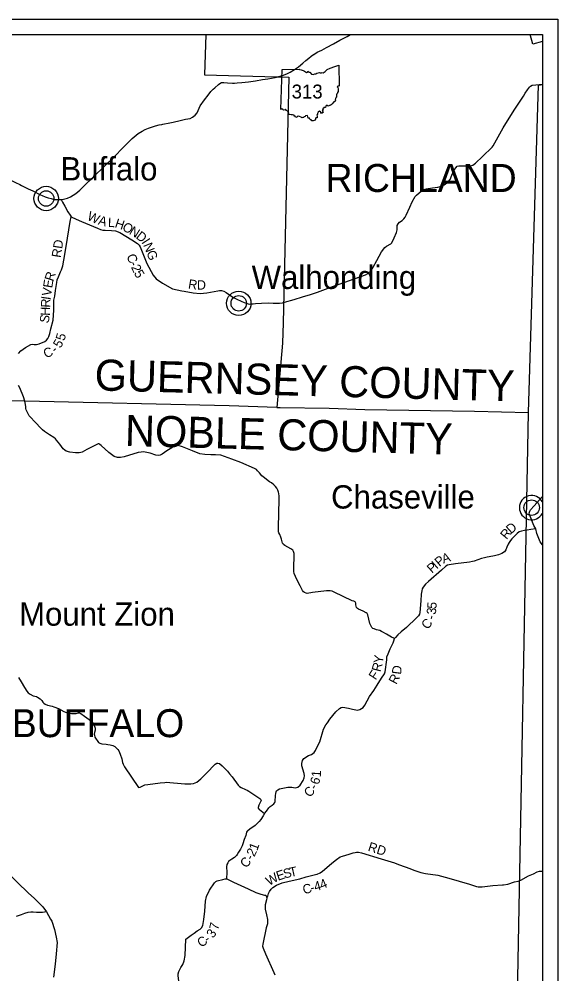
# Model space of a CAD drawing. Extents: x -452339 to 6403467, y -1 to 1814750.
# Drawn here: x -362512 to -345163, y 1631137 to 1661857 of the extents above; entities that cross this region are included whole.
import ezdxf

# ---------------------------------------------------------------- set-up
doc = ezdxf.new("R2010")
doc.units = 0
for name, color, linetype in [('Default', 7, 'Continuous'), ('GM_X_Adjacent_County_Text', 7, 'Continuous'), ('GM_X_County', 7, 'Continuous'), ('GM_X_County_Road', 7, 'Continuous'), ('GM_X_County_Road_Text', 7, 'Continuous'), ('GM_X_Minor_River_Text', 7, 'Continuous'), ('GM_X_Section', 7, 'Continuous'), ('GM_X_Section_Text', 7, 'Continuous'), ('GM_X_Township_Subdivision_Text', 7, 'Continuous')]:
    doc.layers.add(name, color=color, linetype=linetype)

msp = doc.modelspace()

# ---------------------------------------------------------------- linework, layer by layer
at = {"layer": 'Default'}
for p, q in [((-403040, 1661357), (-345663, 1661357)), ((-345663, 1661357), (-345663, 1603979)), ((-354084, 1658949), (-354043, 1660240))]:
    msp.add_line(p, q, dxfattribs=at)
msp.add_lwpolyline([(-403540, 1661857), (-345163, 1661857), (-345163, 1603479), (-403540, 1603479)], close=True, dxfattribs=at)
for points in [[(-354043, 1660240), (-353470, 1660248), (-353479, 1660232), (-353425, 1660229), (-353368, 1660202), (-353319, 1660184), (-353260, 1660143), (-353225, 1660144), (-353210, 1660178), (-353183, 1660151), (-353150, 1660147), (-353094, 1660085), (-353048, 1660072), (-352993, 1660093), (-352952, 1660096), (-352922, 1660117), (-352843, 1660135), (-352821, 1660124), (-352779, 1660127), (-352758, 1660135), (-352722, 1660127), (-352659, 1660175), (-352593, 1660230), (-352492, 1660282), (-352341, 1660331), (-352221, 1660376), (-352204, 1659705)], [(-353036, 1653028), (-352904, 1653069), (-352385, 1653265), (-351363, 1653626), (-351278, 1653673), (-351177, 1653770), (-351108, 1653878), (-350990, 1654089), (-350840, 1654366), (-350735, 1654511), (-350682, 1654554), (-350540, 1654623), (-350507, 1654661), (-350432, 1654816), (-350360, 1654990), (-350335, 1655078), (-350338, 1655170), (-350334, 1655214), (-350310, 1655274), (-350265, 1655319), (-350181, 1655382), (-350128, 1655428), (-350082, 1655488), (-350047, 1655553), (-349933, 1655808), (-349855, 1655980), (-349762, 1656147), (-349719, 1656193), (-349554, 1656333), (-349494, 1656371), (-349401, 1656400), (-349197, 1656426), (-349033, 1656452), (-348955, 1656468), (-348822, 1656528), (-348712, 1656607), (-348633, 1656695), (-348574, 1656838), (-348526, 1656964), (-348483, 1657032), (-348455, 1657075), (-348411, 1657121), (-348355, 1657138), (-347981, 1657131), (-347899, 1657152), (-347818, 1657217), (-347592, 1657431), (-347284, 1657733), (-347243, 1657782), (-347196, 1657880), (-346922, 1658358), (-346567, 1658929), (-346273, 1659378), (-346217, 1659469), (-346143, 1659577), (-346077, 1659665), (-346042, 1659700), (-345992, 1659728), (-345876, 1659743), (-345663, 1659759)], [(-352204, 1659705), (-352222, 1659696), (-352249, 1659701), (-352267, 1659682), (-352244, 1659651), (-352234, 1659617), (-352243, 1659581), (-352234, 1659551), (-352240, 1659526), (-352257, 1659500), (-352263, 1659477), (-352278, 1659451), (-352277, 1659437), (-352291, 1659426), (-352288, 1659384), (-352295, 1659361), (-352293, 1659341), (-352316, 1659336), (-352311, 1659319), (-352325, 1659306), (-352322, 1659284), (-352338, 1659270), (-352323, 1659242), (-352335, 1659233), (-352346, 1659199), (-352375, 1659192), (-352433, 1659130), (-352454, 1659106), (-352476, 1659100), (-352489, 1659076), (-352518, 1659076), (-352561, 1659059), (-352589, 1659088), (-352637, 1659053), (-352643, 1659013), (-352704, 1659014), (-352702, 1658994), (-352716, 1658988), (-352728, 1658968), (-352721, 1658931), (-352750, 1658922), (-352746, 1658901), (-352728, 1658888), (-352720, 1658848), (-352750, 1658856), (-352775, 1658822), (-352801, 1658830), (-352793, 1658859), (-352837, 1658894), (-352878, 1658866), (-352899, 1658822), (-352900, 1658792), (-352930, 1658774), (-352910, 1658732), (-352914, 1658703), (-352914, 1658675), (-352952, 1658676), (-352976, 1658602)], [(-352976, 1658602), (-353042, 1658588), (-353088, 1658580), (-353105, 1658613), (-353138, 1658631), (-353160, 1658665), (-353207, 1658669), (-353218, 1658716), (-353224, 1658754), (-353289, 1658745), (-353306, 1658721), (-353330, 1658715), (-353343, 1658692), (-353375, 1658690), (-353409, 1658679), (-353431, 1658702), (-353486, 1658725), (-353511, 1658737), (-353563, 1658718), (-353574, 1658696), (-353615, 1658706), (-353625, 1658730), (-353650, 1658738), (-353656, 1658763), (-353709, 1658777), (-353750, 1658772), (-353822, 1658792), (-353827, 1658826), (-353852, 1658867), (-353864, 1658896), (-353910, 1658918), (-353919, 1658952), (-353934, 1658951), (-353947, 1658937), (-353998, 1658931), (-354018, 1658944), (-354047, 1658968), (-354084, 1658949)], [(-361158, 1656055), (-361115, 1655967), (-361042, 1655834), (-360943, 1655660), (-360871, 1655545), (-360838, 1655500), (-360678, 1655421), (-360498, 1655343), (-359990, 1655125), (-359895, 1655088), (-359820, 1655071), (-359741, 1655063), (-359535, 1655058), (-359411, 1655045), (-359272, 1654990), (-358878, 1654758), (-358694, 1654634), (-358642, 1654578), (-358616, 1654529), (-358400, 1653988), (-358190, 1653618), (-358097, 1653500), (-357891, 1653357), (-357573, 1653183), (-357273, 1653116), (-357194, 1653100), (-356909, 1653045), (-356677, 1653031), (-356466, 1653046), (-356113, 1653113), (-356064, 1653121), (-355998, 1653123), (-355924, 1653105), (-355849, 1653060), (-355633, 1652907), (-355505, 1652848), (-355365, 1652777), (-355269, 1652734), (-355139, 1652691), (-355096, 1652687), (-355028, 1652693), (-354973, 1652693), (-354900, 1652708), (-354705, 1652721), (-354470, 1652723), (-354332, 1652720), (-354230, 1652713), (-354132, 1652718), (-354034, 1652730), (-353993, 1652742), (-353963, 1652751)], [(-362527, 1651103), (-362460, 1651181), (-362302, 1651291), (-362135, 1651383), (-362085, 1651396), (-362029, 1651390), (-361952, 1651383), (-361868, 1651412), (-361681, 1651487), (-361627, 1651529), (-361585, 1651584), (-361554, 1651642), (-361521, 1651746), (-361493, 1651893), (-361414, 1652169), (-361398, 1652493), (-361398, 1652704), (-361389, 1652809), (-361360, 1652940), (-361339, 1653125), (-361301, 1653386), (-361284, 1653466), (-361246, 1653567), (-361179, 1653727), (-361145, 1653790), (-361103, 1653921), (-361036, 1654279), (-360958, 1654810), (-360868, 1655343), (-360838, 1655500)], [(-353963, 1652751), (-353654, 1652840), (-353385, 1652923), (-353134, 1652998), (-353036, 1653028)], [(-362329, 1649567), (-362373, 1649707), (-362491, 1649998), (-362527, 1650069)], [(-345871, 1645453), (-346031, 1645431), (-346156, 1645411), (-346244, 1645400), (-346340, 1645382), (-346415, 1645356), (-346480, 1645305), (-346564, 1645223), (-346647, 1645134), (-346694, 1645078), (-346733, 1645019), (-346764, 1644961), (-346803, 1644863), (-346838, 1644784), (-346858, 1644748), (-346887, 1644714), (-346964, 1644667), (-347080, 1644619), (-347207, 1644590), (-347375, 1644560), (-347446, 1644547), (-347530, 1644524), (-347622, 1644501), (-347864, 1644418), (-347916, 1644403), (-348012, 1644384), (-348459, 1644326), (-348662, 1644296), (-348714, 1644285), (-348769, 1644256), (-348910, 1644131), (-349326, 1643766), (-349423, 1643677), (-349500, 1643580), (-349531, 1643522), (-349546, 1643464), (-349563, 1643350), (-349578, 1643138), (-349613, 1642768), (-349621, 1642710), (-349648, 1642658), (-349711, 1642589), (-350043, 1642282), (-350205, 1642138), (-350313, 1642045), (-350394, 1641955), (-350426, 1641932), (-350450, 1641938), (-350516, 1641976), (-350681, 1642068), (-350798, 1642128), (-350838, 1642158), (-350896, 1642181), (-351009, 1642207), (-351081, 1642234), (-351121, 1642252), (-351154, 1642287), (-351217, 1642406), (-351283, 1642687), (-351307, 1642735), (-351334, 1642758), (-351430, 1642811), (-351581, 1642867), (-351621, 1642892), (-351647, 1642930), (-351665, 1643015), (-351671, 1643061), (-351683, 1643085), (-351696, 1643103), (-351730, 1643124), (-351786, 1643140), (-352082, 1643284), (-352365, 1643422), (-352427, 1643447), (-352492, 1643462), (-352617, 1643458), (-353068, 1643403), (-353232, 1643379), (-353272, 1643382), (-353324, 1643405), (-353350, 1643433), (-353383, 1643474), (-353459, 1643627), (-353543, 1643782), (-353614, 1643923), (-353656, 1644018), (-353668, 1644082), (-353670, 1644237), (-353655, 1644571), (-353652, 1644661), (-353662, 1644697), (-353673, 1644725), (-353701, 1644768), (-353764, 1644811), (-353955, 1644925), (-353995, 1644952), (-354014, 1644972), (-354028, 1644999), (-354060, 1645125), (-354086, 1645192), (-354119, 1645274), (-354150, 1645333), (-354158, 1645359), (-354163, 1645515), (-354140, 1646397), (-354141, 1646437), (-354143, 1646509), (-354145, 1646595), (-354163, 1646637), (-354184, 1646696), (-354215, 1646760), (-354253, 1646817), (-354306, 1646872), (-354383, 1646933), (-354449, 1646974), (-354546, 1647043), (-354613, 1647094), (-354691, 1647163), (-354775, 1647258), (-354833, 1647325), (-354868, 1647362), (-354928, 1647402), (-355376, 1647595), (-355657, 1647702), (-355898, 1647788), (-356021, 1647823), (-356190, 1647837), (-356334, 1647833), (-356535, 1647845), (-356693, 1647874), (-356929, 1647961), (-357245, 1648092), (-357385, 1648139), (-357446, 1648138), (-357525, 1648105), (-357597, 1648065), (-357752, 1647963), (-357910, 1647854), (-357967, 1647825), (-358015, 1647815), (-358108, 1647830), (-358295, 1647892), (-358401, 1647915), (-358510, 1647932), (-358578, 1647927), (-358680, 1647912), (-359127, 1647770), (-359249, 1647747), (-359345, 1647750), (-359450, 1647787), (-359622, 1647913), (-359864, 1648142), (-359909, 1648174), (-359935, 1648186), (-359963, 1648189), (-360011, 1648175), (-360328, 1648004), (-360485, 1647925), (-360521, 1647912), (-360579, 1647904), (-360694, 1647903), (-360874, 1647923), (-360993, 1647954), (-361041, 1647983), (-361094, 1648033), (-361205, 1648183), (-361303, 1648310), (-361343, 1648354), (-361396, 1648399), (-361535, 1648484), (-361694, 1648586), (-361763, 1648642), (-361828, 1648717), (-361960, 1648861), (-362182, 1649087), (-362282, 1649287), (-362291, 1649324), (-362297, 1649385), (-362309, 1649454), (-362329, 1649567)], [(-354219, 1637028), (-354219, 1637029), (-354214, 1637039), (-354182, 1637061), (-354129, 1637091), (-353965, 1637127), (-353861, 1637147), (-353728, 1637146), (-353620, 1637125), (-353532, 1637148), (-353460, 1637206), (-353367, 1637357), (-353334, 1637442), (-353318, 1637506), (-353331, 1637582), (-353403, 1637832), (-353411, 1637904), (-353390, 1638004), (-353342, 1638065), (-353191, 1638160), (-353099, 1638201), (-353009, 1638265), (-352964, 1638324), (-352905, 1638463), (-352826, 1638607), (-352710, 1639009), (-352631, 1639148), (-352580, 1639220), (-352504, 1639335), (-352310, 1639569), (-352196, 1639672), (-352139, 1639712), (-352089, 1639719), (-351902, 1639682), (-351772, 1639657), (-351619, 1639626), (-351545, 1639642), (-351491, 1639677), (-351431, 1639703), (-351380, 1639778), (-351224, 1640061), (-351093, 1640259), (-350982, 1640432), (-350843, 1640647), (-350746, 1640792), (-350723, 1640858), (-350675, 1641247), (-350666, 1641334), (-350631, 1641432), (-350564, 1641591), (-350471, 1641786), (-350445, 1641858), (-350426, 1641932)], [(-362533, 1640668), (-362449, 1640537), (-362336, 1640349), (-362266, 1640236), (-362219, 1640183), (-362160, 1640132), (-362061, 1640085), (-361951, 1640059), (-361915, 1640042), (-361836, 1639985), (-361783, 1639928), (-361748, 1639885), (-361719, 1639845), (-361675, 1639818), (-361596, 1639787), (-361444, 1639752), (-361389, 1639731), (-361241, 1639673), (-361069, 1639580), (-360964, 1639536), (-360902, 1639529), (-360824, 1639513), (-360678, 1639515), (-360596, 1639533), (-360568, 1639537), (-360528, 1639520), (-360408, 1639434), (-360178, 1639264), (-360147, 1639232), (-360104, 1639149), (-360078, 1639080), (-360066, 1639038), (-360065, 1638982), (-360083, 1638899), (-360091, 1638855), (-360088, 1638813), (-360073, 1638755), (-359958, 1638583), (-359915, 1638556), (-359843, 1638543), (-359707, 1638531), (-359655, 1638522), (-359581, 1638512), (-359492, 1638485), (-359432, 1638458), (-359381, 1638407), (-359330, 1638354), (-359299, 1638310), (-359252, 1638211), (-359201, 1638052), (-359179, 1637938), (-359164, 1637890), (-359114, 1637795), (-358666, 1637130), (-358609, 1637145), (-358506, 1637197), (-358461, 1637218), (-358367, 1637236), (-357974, 1637283), (-357822, 1637298), (-357776, 1637302), (-357173, 1637253), (-356985, 1637251), (-356896, 1637266), (-356786, 1637310), (-356662, 1637415), (-356475, 1637596), (-356200, 1637880), (-356143, 1637915), (-356113, 1637917), (-356061, 1637904), (-355977, 1637831), (-355914, 1637764), (-355803, 1637661), (-355732, 1637571), (-355650, 1637473), (-355461, 1637212), (-355415, 1637164), (-355361, 1637129), (-355218, 1637068), (-355168, 1637046), (-355110, 1637016), (-354757, 1636780), (-354727, 1636749), (-354719, 1636725), (-354723, 1636698), (-354788, 1636568), (-354815, 1636493), (-354811, 1636471), (-354779, 1636426), (-354777, 1636424)], [(-354608, 1636296), (-354542, 1636377), (-354467, 1636484), (-354431, 1636524), (-354361, 1636571), (-354307, 1636613), (-354278, 1636647), (-354262, 1636688), (-354255, 1636878), (-354248, 1636942), (-354234, 1636994), (-354219, 1637028)], [(-354777, 1636424), (-354775, 1636422), (-354608, 1636296), (-354655, 1636226), (-354732, 1636109), (-354780, 1636039), (-354810, 1636005), (-354911, 1635916), (-355079, 1635792), (-355150, 1635742), (-355166, 1635726), (-355186, 1635695), (-355215, 1635593), (-355265, 1635456), (-355310, 1635320), (-355333, 1635261), (-355387, 1635153), (-355444, 1635056), (-355485, 1634978), (-355509, 1634946), (-355581, 1634881), (-355665, 1634828), (-355722, 1634788), (-355764, 1634757), (-355792, 1634709), (-355818, 1634655), (-355829, 1634583), (-355828, 1634408), (-355834, 1634196), (-355806, 1634180), (-355609, 1634089), (-355141, 1633872), (-354888, 1633758), (-354729, 1633703), (-354605, 1633674), (-354571, 1633666), (-354532, 1633580), (-354548, 1633524), (-354584, 1633355), (-354592, 1633273), (-354585, 1633225), (-354548, 1633039), (-354515, 1632883), (-354513, 1632831), (-354518, 1632750), (-354553, 1632616), (-354661, 1632094), (-354673, 1632034), (-354655, 1631964), (-354579, 1631784), (-354306, 1631181), (-354274, 1631105)], [(-354532, 1633580), (-354506, 1633642), (-354477, 1633725), (-354445, 1633787), (-354392, 1633861), (-354338, 1633916), (-354226, 1633987), (-354037, 1634066), (-353813, 1634124), (-353471, 1634200), (-353265, 1634256), (-352971, 1634330), (-352913, 1634349), (-352817, 1634391), (-352742, 1634446), (-352608, 1634563), (-352439, 1634701), (-352288, 1634820), (-352174, 1634899), (-352098, 1634929), (-351884, 1634991), (-351760, 1635030), (-351696, 1635046), (-351650, 1635055), (-351584, 1635055), (-351482, 1635034), (-350852, 1634840), (-350428, 1634709), (-350299, 1634658), (-350085, 1634583), (-349928, 1634530), (-349797, 1634477), (-349641, 1634416), (-349581, 1634396), (-349422, 1634371), (-349025, 1634314), (-348678, 1634216), (-348012, 1634020), (-347789, 1633954), (-347735, 1633942), (-347606, 1633943), (-347254, 1633976), (-346951, 1634003), (-346912, 1634006)], [(-346912, 1634006), (-346774, 1634019), (-346558, 1634099), (-346448, 1634120), (-346357, 1634157), (-346113, 1634295), (-345951, 1634360), (-345830, 1634420), (-345754, 1634441), (-345663, 1634445)], [(-361633, 1633132), (-361756, 1633116), (-361884, 1633109), (-361956, 1633114), (-362062, 1633125), (-362138, 1633123), (-362230, 1633110), (-362334, 1633083), (-362445, 1633040), (-362605, 1632985)], [(-357270, 1628817), (-357270, 1628818), (-357265, 1628856), (-357275, 1628936), (-357318, 1629084), (-357332, 1629193), (-357324, 1629407), (-357306, 1629605), (-357300, 1629697), (-357296, 1630170), (-357303, 1630602), (-357311, 1630676), (-357363, 1630918), (-357387, 1631075), (-357387, 1631139), (-357373, 1631213), (-357301, 1631343), (-357237, 1631443), (-357192, 1631553), (-357162, 1631726), (-357141, 1632254)]]:
    msp.add_lwpolyline(points, dxfattribs=at)
at = {"layer": 'GM_X_County_Road'}
for points in [[(-357880, 1658474), (-357828, 1658484), (-357711, 1658507), (-357547, 1658543), (-357329, 1658592), (-357154, 1658633), (-357006, 1658658), (-356924, 1658699), (-356839, 1658764), (-356774, 1658846), (-356679, 1659070), (-356539, 1659264), (-356427, 1659412), (-356336, 1659527), (-356265, 1659603), (-356212, 1659646), (-356096, 1659752), (-356047, 1659789), (-355995, 1659812), (-355921, 1659815), (-355805, 1659809), (-355642, 1659793), (-355572, 1659791), (-355488, 1659802), (-355338, 1659818), (-355130, 1659840), (-354900, 1659868), (-354672, 1659910), (-354498, 1659935), (-354265, 1659980), (-354031, 1660040), (-353892, 1660097), (-353783, 1660153), (-353644, 1660239), (-353519, 1660326), (-353381, 1660438), (-353278, 1660522), (-353181, 1660604), (-353112, 1660661), (-353034, 1660714), (-353021, 1660723), (-352912, 1660789), (-352769, 1660861), (-352610, 1660948), (-352392, 1661062), (-352183, 1661176), (-351947, 1661298), (-351842, 1661357)], [(-361767, 1656176), (-361672, 1656137), (-361580, 1656108), (-361481, 1656081), (-361377, 1656053), (-361250, 1656053), (-361158, 1656055), (-361083, 1656066), (-360958, 1656098), (-360858, 1656141), (-360766, 1656188), (-360680, 1656248), (-360555, 1656355), (-360430, 1656486), (-359453, 1657427), (-359158, 1657725), (-358978, 1657905), (-358871, 1658017), (-358680, 1658171), (-358554, 1658253), (-358447, 1658307), (-358349, 1658351), (-358248, 1658384), (-358124, 1658422), (-358000, 1658452), (-357920, 1658467), (-357880, 1658474)], [(-362751, 1656664), (-362623, 1656595), (-362490, 1656531), (-362434, 1656504), (-362215, 1656398), (-362069, 1656327), (-361825, 1656200), (-361767, 1656176)], [(-345663, 1644946), (-345732, 1645042), (-345780, 1645141), (-345846, 1645306), (-345871, 1645453), (-345943, 1645568), (-346079, 1645918), (-346086, 1645962), (-346066, 1646030), (-346043, 1646064), (-345932, 1646193), (-345847, 1646292), (-345663, 1646502)], [(-362937, 1634447), (-362209, 1633731), (-362029, 1633572), (-361750, 1633296), (-361633, 1633132), (-361497, 1632896), (-361460, 1632832), (-361371, 1632567), (-361322, 1632324), (-361291, 1632146), (-361320, 1631781), (-361353, 1631446), (-361401, 1631037)]]:
    msp.add_lwpolyline(points, dxfattribs=at)
at = {"layer": 'GM_X_County_Road_Text'}
for centre, radius in [((-361640, 1656085), 393), ((-361640, 1656085), 249), ((-355439, 1652712), 393), ((-355439, 1652712), 249), ((-346010, 1646139), 249)]:
    msp.add_circle(centre, radius, dxfattribs=at)
msp.add_arc((-346010, 1646139), 393, 27.9792, 332.0208, dxfattribs=at)
at = {"layer": 'GM_X_Minor_River_Text'}
msp.add_lwpolyline([(-345663, 1661136), (-345968, 1661052), (-346060, 1661357)], dxfattribs=at)
at = {"layer": 'GM_X_Section'}
msp.add_lwpolyline([(-357141, 1632254), (-356971, 1632384), (-356878, 1632452), (-356776, 1632520), (-356681, 1632580), (-356639, 1632621), (-356599, 1632695), (-356560, 1632892), (-356533, 1633159), (-356506, 1633476), (-356475, 1633627), (-356386, 1633833), (-356224, 1634070), (-356181, 1634105), (-356134, 1634132), (-355956, 1634169), (-355872, 1634194), (-355834, 1634196)], dxfattribs=at)
at = {"layer": 'GM_X_Section_Text'}
for p, q in [((-356504, 1661357), (-356546, 1660061)), ((-356546, 1660061), (-353830, 1659985)), ((-353830, 1659985), (-354011, 1652086)), ((-346105, 1649196), (-345786, 1659733)), ((-345786, 1659733), (-345663, 1659749)), ((-354011, 1652086), (-354029, 1651430)), ((-354029, 1651430), (-354213, 1649357)), ((-362329, 1649567), (-364630, 1649614)), ((-355744, 1649412), (-362329, 1649567)), ((-354213, 1649357), (-355744, 1649412)), ((-354213, 1649357), (-354110, 1649355)), ((-354213, 1649357), (-354110, 1649355)), ((-354110, 1649355), (-352523, 1649334)), ((-352523, 1649334), (-351384, 1649293)), ((-352523, 1649334), (-351384, 1649293)), ((-351384, 1649293), (-347847, 1649245)), ((-351384, 1649293), (-347847, 1649245)), ((-347847, 1649245), (-346105, 1649196)), ((-347847, 1649245), (-346105, 1649196)), ((-346510, 1627988), (-346105, 1649196))]:
    msp.add_line(p, q, dxfattribs=at)

# ---------------------------------------------------------------- texts
at = {"layer": 'Default'}
msp.add_text('313', height=447.7, dxfattribs=at).set_placement((-353736, 1659302))
at = {"layer": 'GM_X_Adjacent_County_Text'}
for s, height, rotation, p in [('Buffalo', 750, 0, (-361179, 1656665)), ('Walhonding', 750, 0, (-355024, 1653175)), ('GUERNSEY COUNTY', 1000, 358.4869, (-360089, 1649912)), ('NOBLE COUNTY', 1000, 358.4869, (-359114, 1648123)), ('Chaseville', 750, 0, (-352466, 1646109)), ('Mount Zion', 750, 0, (-362512, 1642340)), ('BUFFALO', 900, 0, (-362746, 1638754))]:
    msp.add_text(s, height=height, rotation=rotation, dxfattribs=at).set_placement(p)
at = {"layer": 'GM_X_County'}
for s, rotation, p in [('W', 336.5322, (-360344, 1655407)), ('A', 344.0822, (-359985, 1655254)), ('L', 357.6294, (-359655, 1655169)), ('H', 341.3185, (-359452, 1655164)), ('O', 330.1652, (-359216, 1655086)), ('N', 328.7101, (-358989, 1654956)), ('D', 321.9148, (-358771, 1654824)), ('RD', 81.0031, (-361172, 1654165)), ('I', 302.7613, (-358581, 1654680)), ('N', 292.2086, (-358521, 1654590)), ('C', 291.4274, (-359059, 1654237)), ('G', 292.3249, (-358421, 1654345)), ('2', 294.9234, (-358914, 1653876)), ('-', 292.4657, (-358967, 1654002)), ('R', 72.1902, (-361415, 1653400)), ('5', 299.6253, (-358824, 1653684)), ('E', 81.0886, (-361447, 1653190)), ('R', 350.6538, (-357083, 1653196)), ('D', 0.8434, (-356783, 1653152)), ('V', 81.4147, (-361486, 1652929)), ('R', 87.6927, (-361512, 1652570)), ('I', 82.0278, (-361503, 1652808)), ('H', 88.1853, (-361521, 1652307)), ('S', 78.3695, (-361568, 1652053)), ('5', 58.959, (-361183, 1651248)), ('5', 75.0386, (-361051, 1651491)), ('C', 23.1227, (-361653, 1650938)), ('-', 41.4708, (-361339, 1651090)), ('R', 50.7251, (-346818, 1645095)), ('D', 42.0803, (-346670, 1645278)), ('P', 40.0246, (-348977, 1644225)), ('A', 18.0444, (-348849, 1644340)), ('P', 41.4094, (-349220, 1644011)), ('I', 41.3438, (-349068, 1644145)), ('3', 84.8445, (-349095, 1642687)), ('5', 84.8487, (-349078, 1642871)), ('-', 75.0151, (-349136, 1642513)), ('C', 49.2539, (-349366, 1642197)), ('Y', 82.1193, (-350806, 1641110)), ('R', 75.4588, (-350876, 1640835)), ('F', 56.555, (-351030, 1640570)), ('R', 62.1188, (-350367, 1640430)), ('D', 82.6809, (-350217, 1640757)), ('6', 73.1837, (-352867, 1637207)), ('1', 86.1289, (-352800, 1637457)), ('C', 50.4338, (-353143, 1636795)), ('-', 61.9541, (-352949, 1637039)), ('1', 69.6432, (-354845, 1635084)), ('RD', 342.4992, (-351301, 1635102)), ('2', 63.873, (-354939, 1634888)), ('-', 62.5198, (-355000, 1634771)), ('C', 49.3923, (-355202, 1634522)), ('W', 30.5301, (-354458, 1633962)), ('E', 18.874, (-354174, 1634132)), ('S', 14.1999, (-353968, 1634203)), ('T', 12.7566, (-353773, 1634252)), ('C', 14.4215, (-353340, 1633697)), ('4', 15.9741, (-352973, 1633792)), ('4', 22.0714, (-352763, 1633854)), ('-', 14.7411, (-353099, 1633758)), ('7', 77.0313, (-356104, 1632534)), ('3', 54.5647, (-356264, 1632267)), ('C', 33.6608, (-356654, 1631975)), ('-', 35.8265, (-356439, 1632119))]:
    msp.add_text(s, height=300, rotation=rotation, dxfattribs=at).set_placement(p)
at = {"layer": 'GM_X_Township_Subdivision_Text'}
msp.add_text('RICHLAND', height=900, rotation=0, dxfattribs=at).set_placement((-352643, 1656295))

doc.saveas('drawing.dxf')
